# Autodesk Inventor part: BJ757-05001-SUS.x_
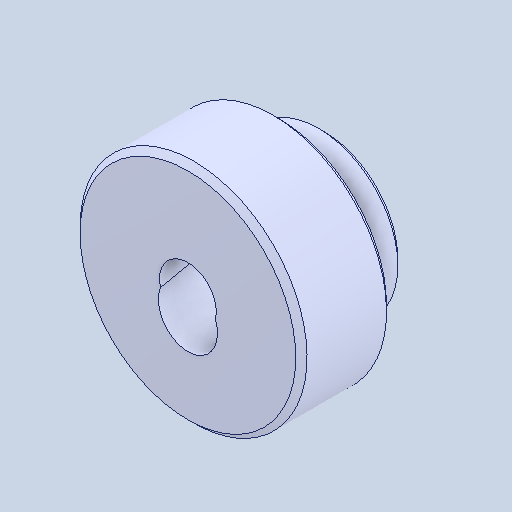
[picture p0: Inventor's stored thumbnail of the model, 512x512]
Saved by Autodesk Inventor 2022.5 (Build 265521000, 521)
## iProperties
Created: 2024-05
Part Number: BJ757-05001-SUS.x_
Material: 一般
Document SubType Name: Modeling
Designer: ImaoCorp
Density: 1 g/cm^3
Appearance: 既定
Author: ImaoCorp
Sending System: SOLIDWORKS 2022-2022290
MC: AMD64
MC_MODEL: Intel64 Family 6 Model 60 Stepping 3, GenuineIntel
OS: Windows_NT
FRU: Parasolid Version 33.1, build 260,  4-25-2022
FORMAT: text
GUISE: transmit
KEY: FILEBJ757-05001-SUS.x_t
DATE: Tue May 21 08:47:13 2024
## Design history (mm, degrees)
feature "Base1"
node "ソリッド1"
